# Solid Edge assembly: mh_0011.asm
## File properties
Title: remote_unit
Author: edge
Template: normal.asm
Last saved by: edge
Revision: 35
Application: Solid Edge
Username: kiyo
文書内容のタイプ: 1
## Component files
mh_0023.asm
mh_0022.par
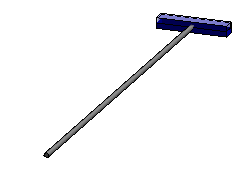
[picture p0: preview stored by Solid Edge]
